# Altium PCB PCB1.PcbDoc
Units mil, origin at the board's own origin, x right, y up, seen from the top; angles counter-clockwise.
Board outline 2945 x 2892.01 mil, 2 copper layers (Top Layer, Bottom Layer); 40 components, 36 nets, 180 pads, 28 vias.
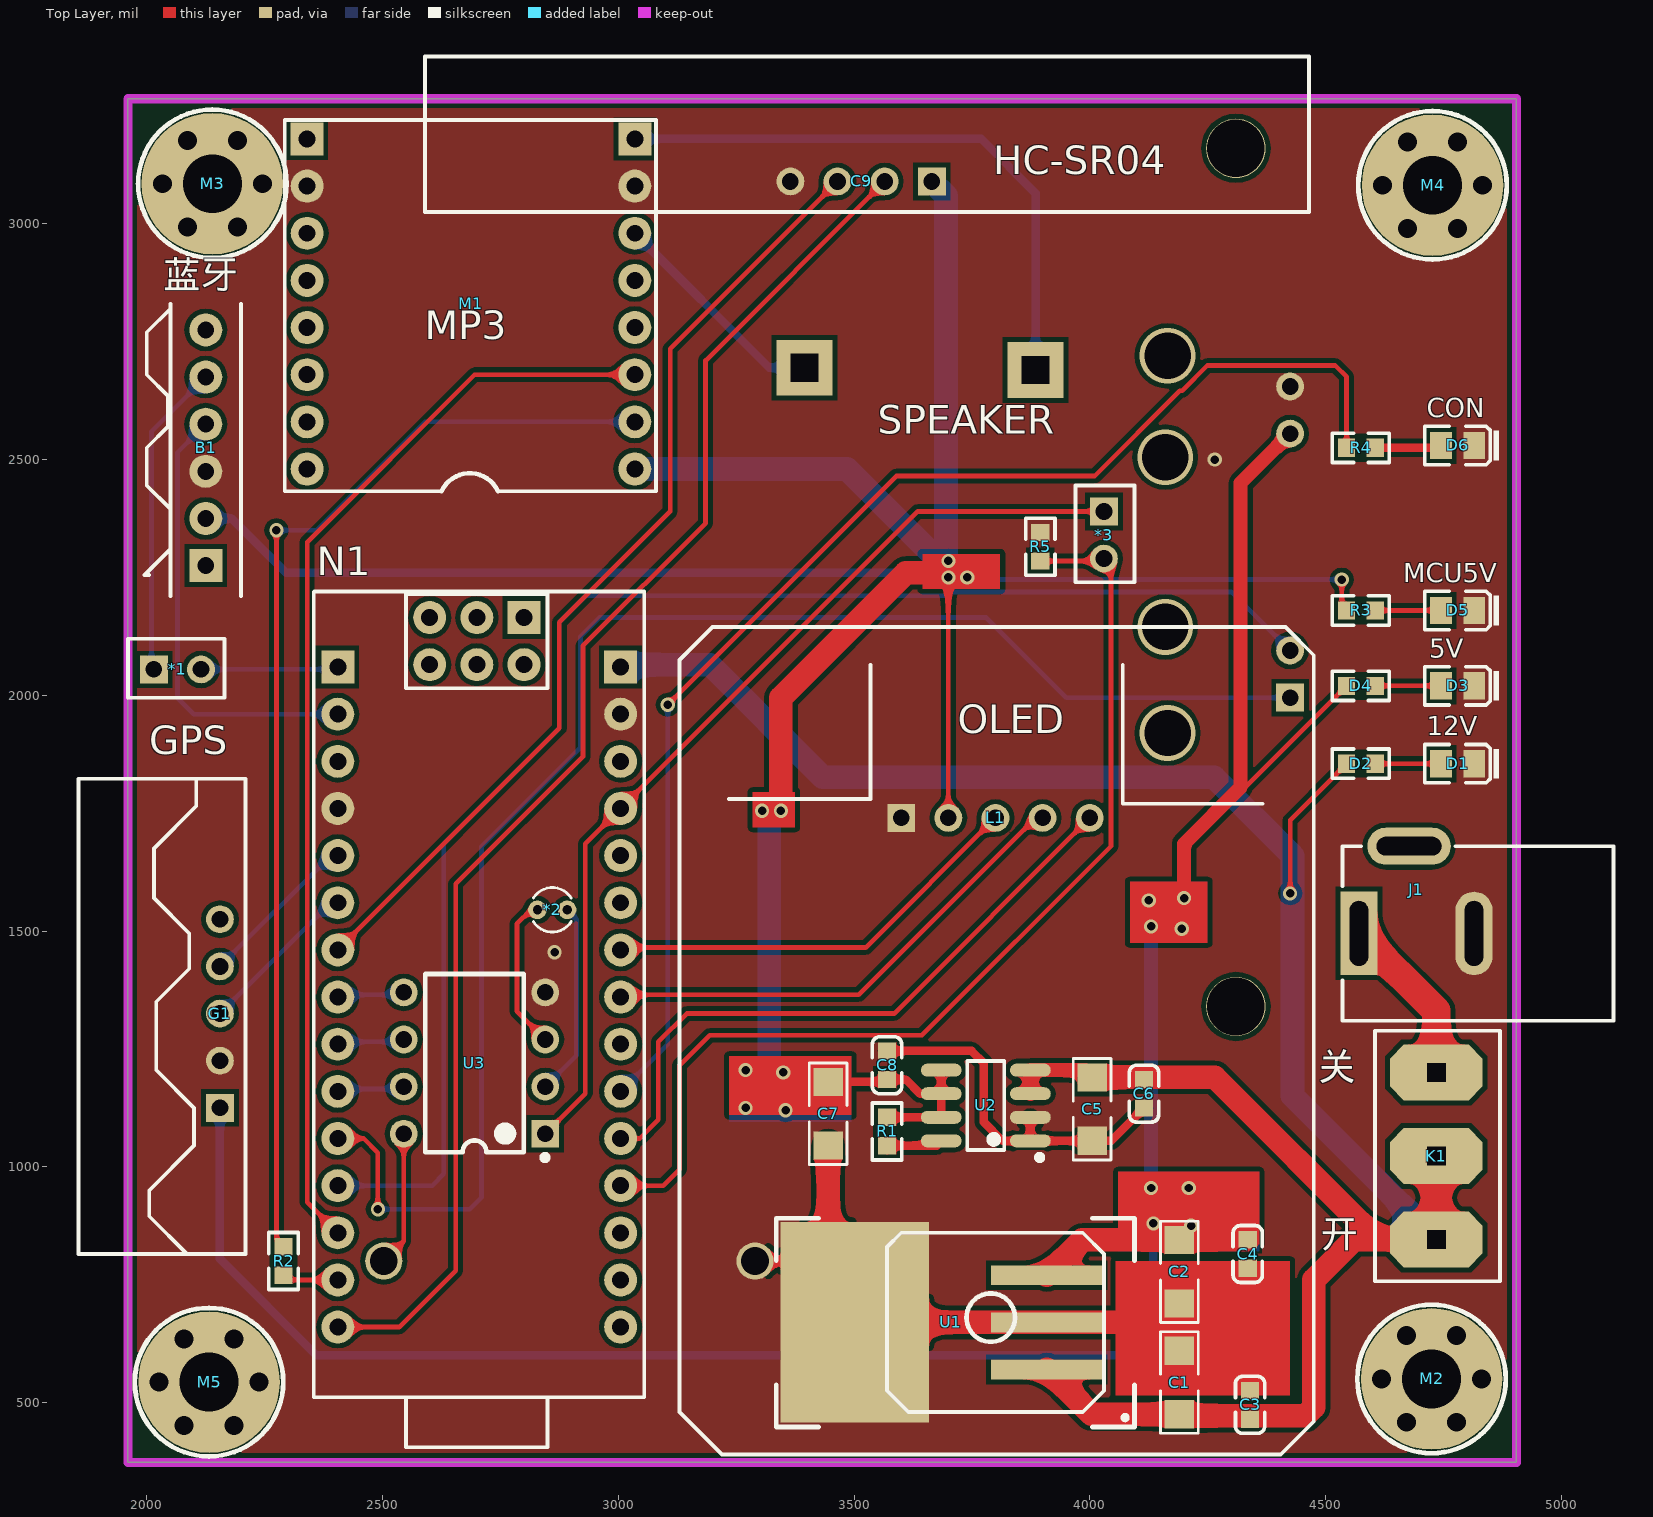
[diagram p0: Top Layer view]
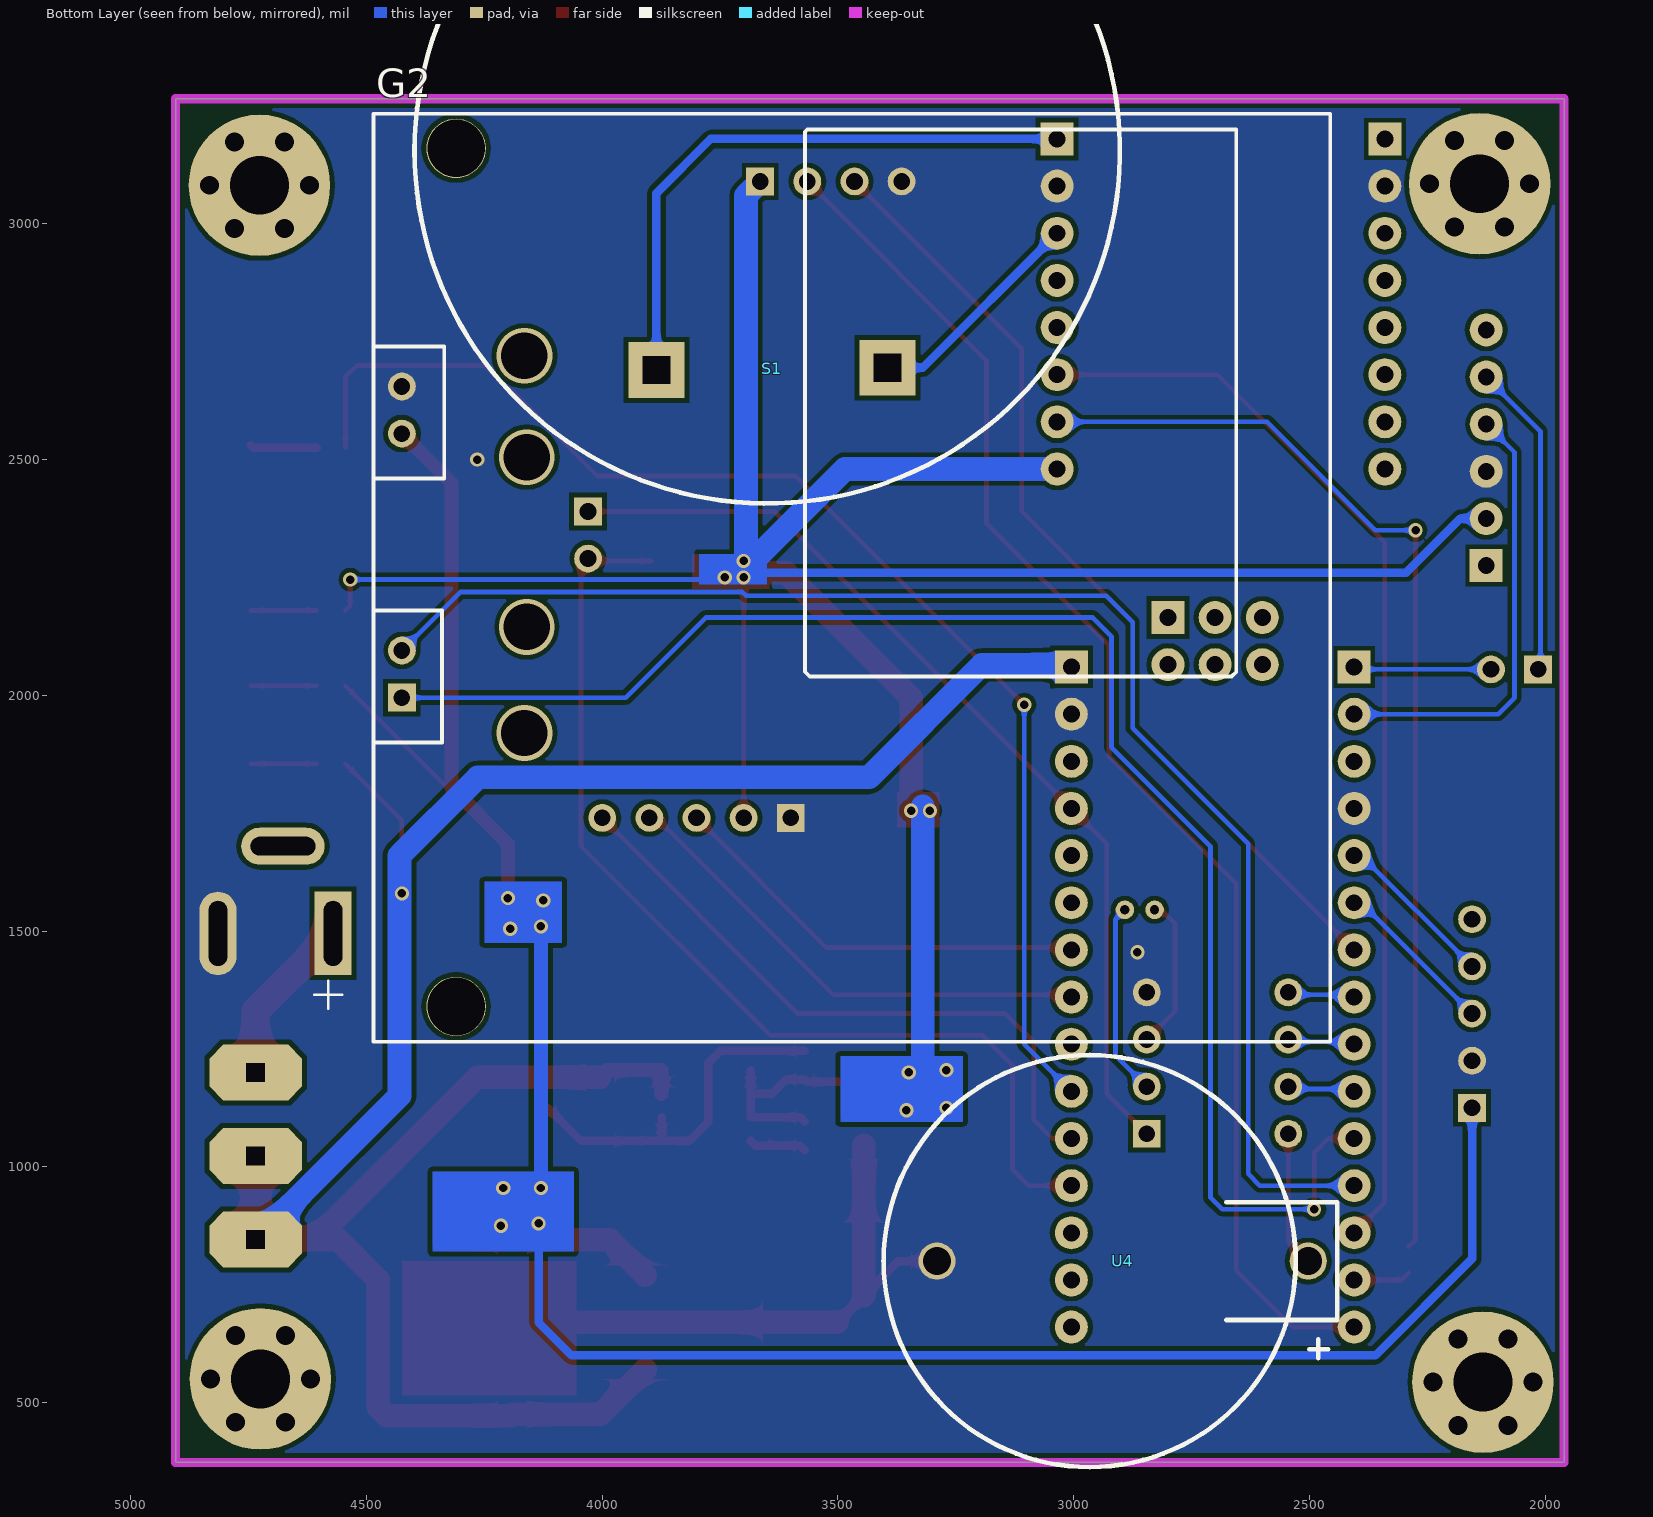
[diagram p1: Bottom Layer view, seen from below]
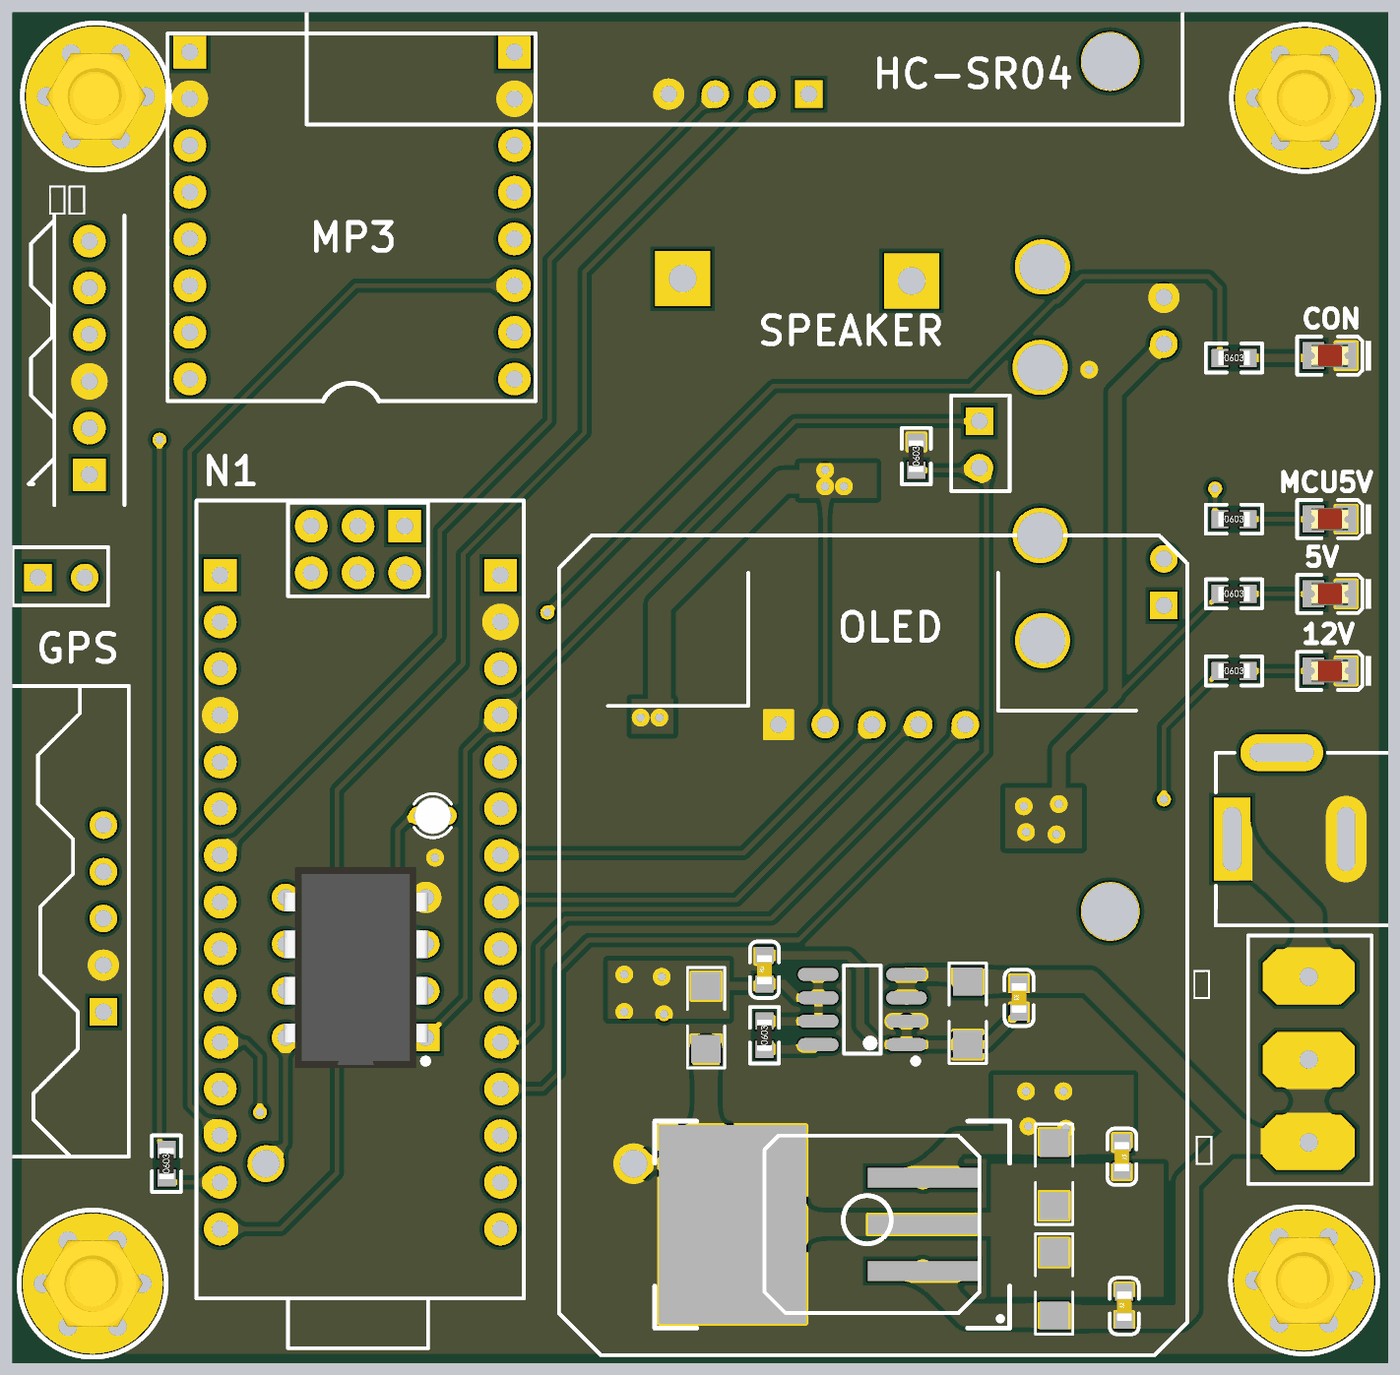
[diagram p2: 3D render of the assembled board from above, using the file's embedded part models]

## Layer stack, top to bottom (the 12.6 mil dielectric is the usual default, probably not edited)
Top Solder: solder mask 0.4, Solder Resist, Dk 3.5
Top Layer: signal copper 1.4
Dielectric 1: dielectric 12.6, FR-4, Dk 4.8
Bottom Layer: signal copper 1.4
Bottom Solder: solder mask 0.4, Solder Resist, Dk 3.5

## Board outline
1960,372.99 4905,372.99 4905,3265 1960,3265

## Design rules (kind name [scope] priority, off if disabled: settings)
Clearance [All] p1: gap=10
ComponentClearance [All] p1 off: gap=10 collisioncheckmode=3 verticalgap=10 showdistances=FALSE
PlaneConnect [All] p1: planeconnectstyle=Direct reliefexpansion=20 reliefentries=4 reliefconductorwidth=10 reliefairgap=10
PolygonConnect [All] p1: connectstyle=Direct reliefconductorwidth=10 reliefentries=4 polygonreliefangle="90 Angle" airgapwidth=10
RoutingVias [All] p1: holewidth=28 width=50 viastyle="Through Hole" minholewidth=28 minwidth=50 maxholewidth=28 maxwidth=50
SolderMaskExpansion [All] p1: expansion=4
Width [All] p1: maxlimit=99 minlimit=10 preferedwidth=18 minimp=50.000000 maximp=50.000000 favimp=50.000000
28 further rules are at their usual default settings.

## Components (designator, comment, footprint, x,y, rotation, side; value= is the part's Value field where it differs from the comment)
*1 "跳帽" 跳帽 1840,2120 r0 top
*2 "osc" OSC-2X6-LI 2860,1545 r0 top
*3 "光敏电阻" 跳帽 4095,2565 r270 top
B1 "BlueTOOLS" BLUETOOTH 2050,2455 r90 top
C1 "10uF" 1206 4190,475 r90 top
C2 "10uF" 1206 4190,844.65 r270 top
C3 "104" 0603_C 4340,495 r90 top
C4 "104" 0603_C 4335,815 r270 top
C5 "10uF" 1206 4005,1189.65 r270 top
C6 "104" 0603_C 4115,1155 r90 top
C7 "10uF" 1206 3445,1180 r270 top
C8 "103" 0603_C 3570,1215.31 r90 top
C9 "HC-SR04" HC-SR04 4415,3310 r180 top
D1 "蓝灯 0805" 0805_LED_S1 4780,1855 r180 top
D2 "Res2" 0603_R 4575,1855 r0 top
D3 "蓝灯 0805" 0805_LED_S1 4780,2020 r180 top
D4 "Res2" 0603_R 4575,2020 r0 top
D5 "蓝灯 0805" 0805_LED_S1 4780,2180 r180 top
D6 "白灯 0805" 0805_LED_S1 4780,2530 r180 top
G1 "GPS" GPS 1855,815 r90 top
G2 "GPRS" GPRS 4385,1265 r90 bottom
J1 "12DC插座" "DC插座 5.5mm*2.1mm" 4570.91,1495 r180 top
K1 "拨动开关" SW1 4600,755 r0 top
L1 "oled" OLED 3230,450 r0 top
M1 "MP3_MOD" MP3_MOD 3080,3220 r180 top
M2 "HDC3-3M5" M3X4固定孔 4725,550 r0 top
M3 "HDC3-3M5" M3X4固定孔 2139,3085 r0 top
M4 "HDC3-3M5" M3X4固定孔 4727,3081.8 r0 top
M5 "HDC3-3M5" M3X4固定孔 2132,543.2 r0 top
N1 "ArduinoNano" ArduinoNano 3055,510 r90 top
R1 "Res/250K" 0603_R 3570,1075 r90 top
R2 "1K" 0603_R 2290,800 r90 top
R3 "Res2" 0603_R 4575,2180 r0 top
R4 "1.5KΩ (1501) ±1%" 0603_R 4575,2525 r0 top
R5 "1KΩ" 0603_R 3895,2315 r90 top
S1 "SRKER" SPERKER 3650,3155 r180 bottom
U1 "LM2940" LM2940 3715,670 r180 top
U2 "TPS7350" SOIC8 3873.98,1055 r180 top
U3 "DS1302" DS1302 2695,1220 r180 top
U4 "CR2302" BATTERY-2032 2502.6,800 r0 bottom

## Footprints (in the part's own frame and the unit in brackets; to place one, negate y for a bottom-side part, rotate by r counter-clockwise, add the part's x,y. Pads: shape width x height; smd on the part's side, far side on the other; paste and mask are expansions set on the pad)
0603_C [mm]
  rect 0.93x0.98 smd: 1(-0.77,0) 2(0.77,0)
  silkscreen extent -1.54,-0.79 1.54,0.79, body extent -0.8,-0.4 0.8,0.4, height 0.3
0603_R [mm]
  rect 0.93x0.98 smd: 1(-0.77,0) 2(0.77,0)
  silkscreen extent -1.53,-0.79 1.54,0.79, body extent -0.85,-0.4 0.85,0.4, height 0.56
0805_LED_S1 [mm]
  rect 1.16x1.47 smd: A(0.89,0) K(-0.89,0)
  silkscreen extent -2.25,-1.04 1.77,1.03, body extent -1.01,-0.62 1.01,0.62, height 1.1
1206 [mm]
  rect 1.52x1.6 smd: 1(0,0) 2(3.42,0)
  silkscreen extent -1.02,-1.02 4.44,1.02
ArduinoNano [mil] "单片机插口"
  rect 70x70 hole 36: 1(1550,50) 30(1550,650) 36(1655,255)
  round 70 hole 36: 2(1450,50) 3(1350,50) 4(1250,50) 5(1150,50) 6(1050,50) 7(950,50) 8(850,50) 9(750,50) 10(650,50) 11(550,50) 12(450,50) 13(350,50) 14(250,50) 15(150,50) 16(150,650) 17(250,650) 18(350,650) 19(450,650) 20(550,650) 21(650,650) 22(750,650) 23(850,650) 24(950,650) 25(1050,650) 26(1150,650) 27(1250,650) 28(1350,650) 29(1450,650) 31(1555,455) 32(1655,455) 33(1555,355) 34(1655,355) 35(1555,255)
  silkscreen extent -105,0 1710,701
BATTERY-2032 [mm]
  round 2 hole 1.5: 1(0,0) 2(20,0)
  silkscreen extent -1.56,-11.1 22.88,11.1
BLUETOOTH [mil]
  rect 70x70 hole 36: 1(-180,-75)
  round 70 hole 36: 2(-80,-75) 3(20,-75) 4(120,-75) 5(220,-75) 6(320,-75)
  silkscreen extent -245,-150 375,0
"DC插座 5.5mm*2.1mm" [mm]
  rect 2x4.5 hole 1 slot 3.5 at 90 deg: 1(0,0)
  oval 2x4.5 hole 1 slot 3.5 at 90 deg: 2(-6.2,0)
  oval 4.5x2 hole 1 slot 3.5 at 0 deg: 3(-2.7,-4.7)
  silkscreen extent -13.72,-4.7 0.89,4.7
DS1302 [mm] "RTC实时时钟芯片"
  rect 1.5x1.5 hole 0.9: 1(-3.81,3.81)
  round 1.5 hole 0.9: 2(-3.81,1.27) 3(-3.81,-1.27) 4(-3.81,-3.81) 5(3.81,-3.81) 6(3.81,-1.27) 7(3.81,1.27) 8(3.81,3.81)
  silkscreen extent -3.95,-4.8 2.65,5.24, body extent -3.93,-5.46 3.94,5.46, height 5.08
GPRS [mm]
  round 1.5 hole 0.9: 1(32.766,1.016) 2(21.082,1.016) 4(35.306,1.016)
  rect 1.5x1.5 hole 0.9: 3(18.542,1.016)
  round 3.2 hole 3.1: ""(1.905,-1.905) ""(48.133,-1.905)
  silkscreen extent 0,-49 50,2.54
GPS [mm]
  rect 1.5x1.5 hole 0.9: 1(7.874,-7.62)
  round 1.5 hole 0.9: 2(10.414,-7.62) 3(12.954,-7.62) 4(15.494,-7.62) 5(18.034,-7.62)
  silkscreen extent 0,-9 25.6,0
HC-SR04 [mm] "超声波模块"
  rect 1.5x1.5 hole 0.9: 1(19.05,5.588)
  round 1.5 hole 0.9: 2(21.59,5.588) 3(24.13,5.588) 4(26.67,5.588)
  silkscreen extent -1.27,-1.14 46.35,7.24
LM2940 [mm] "LM2940"
  rect 6x1.07 smd: 1(-4.925,2.54) 2(-4.925,0) 3(-4.925,-2.54)
  rect 8x10.8 smd: 2(5.41,0)
  silkscreen extent -9.65,-5.61 9.65,5.64, body extent -4.45,-5.21 4.45,5.21, height 4.65
M3X4固定孔 [mil] "M3铜柱，长：4mm，螺纹长：6mm"
  round 40 hole 40: 1(-106,0) 1(-53,-91.8) 1(-53,91.8) 1(53,-91.8) 1(53,91.8) 1(106,0)
  round 300 hole 125: 1(0,0)
  silkscreen extent -157,-157 157,157, body extent -106,-93 106,93, height 159
MP3_MOD [mil]
  round 70 hole 36: 1(45,740) 2(45,640) 3(45,540) 4(45,440) 5(45,340) 6(45,240) 7(45,140) 10(740,140) 11(740,240) 12(740,340) 13(740,440) 14(740,540) 15(740,640) 16(740,740)
  rect 70x70 hole 36: 8(45,40) 9(740,40)
  silkscreen extent 0,0 787,787
OLED [mm] "0.96寸带五轴按键"
  rect 1.5x1.5 hole 0.9: 1(9.398,32.766)
  round 1.5 hole 0.9: 2(11.938,32.766) 3(14.478,32.766) 4(17.018,32.766) 5(19.558,32.766)
  silkscreen extent -2.54,-1.52 31.62,43.05
OSC-2X6-LI [mm] "脚距：1.6mm"
  round 1 hole 0.5: 1(0.8,0) 2(-0.8,0)
  silkscreen extent -1.02,-1.2 1.02,1.2, body extent -1,-1 1,1, height 7.1
SOIC8 [mm]
  oval 2.2x0.7 smd: 1(0,0) 2(0,-1.27) 3(0,-2.54) 4(0,-3.81) 5(4.8,-3.81) 6(4.8,-2.54) 7(4.8,-1.27) 8(4.8,0)
  silkscreen extent -0.65,-4.31 3.4,1.04
SPERKER [mm]
  rect 3x3 hole 1.5 square: 1(-5.969,-11.811) 2(6.477,-11.684)
  silkscreen extent -19,-19 19,19
SW1 [mm]
  oct 5x3 hole 1 square: 1(3.429,11.303) 2(3.429,6.803) 3(3.429,2.303)
  silkscreen extent 0.13,0.05 6.86,13.55
跳帽 [mm]
  rect 1.5x1.5 hole 0.9: 1(4.445,-1.651)
  round 1.5 hole 0.9: 2(6.985,-1.651)
  silkscreen extent 3.05,-3.17 8.25,0

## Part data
*3: library part 跳帽
C1 C2 C5 C7: library part 电解电容, "Capacitor"
C3 C4 C6 C8: library part 普通电容, "Capacitor"
D1 D3 D5: library part "0805 蓝灯", "发光二极管"
D2 D4 R3: "Resistor"
D6: library part "0805 白灯", "发光二极管"
J1: library part DC插座
R1: library part Res2, "Resistor"
R2: library part "0603 1.1KΩ (1101) 1%", "贴片电阻"
R4 R5: library part "0603 1.5KΩ (1501) 1%", "贴片电阻"
U1: library part 78L05, "CI-78L05"

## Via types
v1: diameter 30, hole 18, Top Layer to Bottom Layer, 24 vias
v2: diameter 118.11, hole 98.43, Top Layer to Bottom Layer, 4 vias

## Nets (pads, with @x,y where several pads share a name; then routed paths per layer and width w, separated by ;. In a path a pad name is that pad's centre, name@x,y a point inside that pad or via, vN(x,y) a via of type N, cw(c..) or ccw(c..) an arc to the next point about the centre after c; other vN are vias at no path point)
5V: *3.1 N1.4 U3.1 | length 2042.2
  Top Layer w10: U3.1 2930,1155 2930,1685 N1.4 3635,2390 *3.1
12V: C1.1 C3.1 C5.1 C6.2 D2.1 K1.2 K1.3 N1.1 U1.1 U2.3 U2.4 | length 5139.3
  Top Layer w10: v1(4425,1580) 4425,1735.31 D2.1
  Top Layer w30: U2.3 U2.4 3989.65,1205 C5.1
  Top Layer w50: U1.1 4003.9,475 C1.1 4192.99,472.01 4457.01,472.01 4475,490 4475,760 4560.67,845.67 4609.33,845.67 ; C5.1 4005.35,1190 4265,1190 4609.33,845.67 ; K1.3 4609.33,845.67
  Top Layer w60: K1.3 K1.2
  Bottom Layer w50: N1.1@3015,2065 3195,2065 3434.06,1825.94 4264.06,1825.94 4430,1660 4430,1150.67 K1.3
B_RX: B1.4 N1.29 | length 959.4
  Bottom Layer w10: B1.4 2065,2515 2065,1995 2100,1960 N1.29
B_TX: *1.2 N1.30 | length 292.1
  Bottom Layer w10: *1.2 2400,2055 N1.30
CONTROL_LED: N1.10 R4.1 | length 2759.5
  Top Layer w10: v1(3105,1980) 3590,2465 4010,2465 4190.94,2645.94 4195.67,2645.94 4249.26,2699.53 4520.47,2699.53 4544.69,2675.31 R4.1
  Bottom Layer w10: N1.10 3105,1260 v1(3105,1980)
DS3V3: U3.8 U4.1 | length 287.6
  Top Layer w10: U4.1 2545,842.4 U3.8
ECHO: C9.3 N1.24 | length 2069.1
  Top Layer w10: N1.24 2875,1930 2875,2155 3110,2390 3110,2735 C9.3
GND: B1.3 C1.2 C2.2 C3.2 C4.2 C5.2 C6.1 C7.2 C8.2 C9.4 D1.K D3.K D5.K D6.K G1.2 G2.4 J1.2 L1.1 M1.7 M1.10 N1.2 N1.27 R5.2 U1.2 U2.1 U2.2 U3.4 U4.2 | length 2446
  Top Layer w18: U4.2 3372,800 3445,727 U1.2@3502,670 ; C8.2 3749.37,1245.63 3775,1220 3775,1095 3815,1055 U2.1 ; U2.2 U2.1 ; C6.1 4045.31,1055 C5.2 U2.1 ; C1.2 4255.67,609.65 C3.2 ; C2.2 4264.69,784.69 C4.2
  Top Layer w50: U1.2@3445,727 C7.2 ; U1.2@3502,670 3908.9,670 4150,670 4150,649.65 C1.2
  other v1: 2865,1455 4265,2500
GPRS_RX: G2.3 N1.20 | length 3316.8
  Top Layer w10: N1.20 2460,1060 2490,1030 v1(2490,910)
  Bottom Layer w10: v1(2490,910) 2685,910 2710,935 2710,1680 2920,1890 2920,2125 2960,2165 3780,2165 3950,1995 G2.3
GPRS_TX: G2.2 N1.19 | length 3134.8
  Bottom Layer w10: N1.19 2605,960 2630,985 2630,1685 2875,1930 2875,2155 2931,2211 3694.94,2211 3703,2219.06 4300.95,2219.06 G2.2
GPS_RX: G1.4 N1.26 | length 347.3
  Bottom Layer w10: G1.4 2390,1660 N1.26
GPS_TX: G1.3 N1.25 | length 347.3
  Bottom Layer w10: G1.3 2390,1560 N1.25
MP3_RX: M1.3 N1.18 | length 2334
  Top Layer w10: N1.18 2340,925 2340,2325 2695,2680 M1.3
MP3_TX: N1.17 R2.1 | length 121.1
  Top Layer w10: R2.1@2290,774.69 2304.68,760 N1.17
Net*1_1: *1.1 B1.5 | length 662.6
  Bottom Layer w10: *1.1@2010,2060 2010,2560 B1.5
Net*2_1: *2.1 U3.2 | length 410.8
  Bottom Layer w10: U3.2 2911.5,1236.5 2911.5,1525 *2.1
Net*2_2: *2.2 U3.3 | length 325.8
  Top Layer w10: *2.2 2815,1545 2785,1515 2785,1330 U3.3
NetD1_A: D1.A D2.2 | length 139.6
  Top Layer w10: D2.2 D1.A
NetD3_A: D3.A D4.2 | length 139.6
  Top Layer w10: D4.2 D3.A
NetD5_A: D5.A R3.2 | length 139.6
  Top Layer w10: R3.2 D5.A
NetD6_A: D6.A R4.2 | length 141.7
  Top Layer w18: R4.2 4739.96,2525 D6.A
NetJ1_1: J1.1 K1.1 | length 363
  Top Layer w60: J1.1 4735,1330.91 K1.1
NetM1_2: M1.2 R2.2 | length 2381.2
  Top Layer w10: v1(2275,2350) 2275,845.32 R2.2
  Bottom Layer w10: v1(2275,2350) 2360,2350 2590,2580 M1.2
NetM1_6: M1.6 S1.2 | length 478.1
  Bottom Layer w18: M1.6 3320,2695 S1.2
NetM1_8: M1.8 S1.1 | length 1272.6
  Bottom Layer w18: M1.8 3770,3180 3885,3065 S1.1
NetR1_1: R1.1 U2.8 | length 123.4
  Top Layer w18: R1.1@3570,1034.69 3580.31,1045 3675,1045 U2.8
PIN_CLK: N1.21 U3.7 | length 132.1
  Bottom Layer w10: N1.21@2415,1165 2540,1165 U3.7
PIN_DAT: N1.22 U3.6 | length 132.1
  Bottom Layer w10: N1.22@2415,1265 2540,1265 U3.6
PIN_RET: N1.23 U3.5 | length 132.1
  Bottom Layer w10: N1.23@2415,1365 2540,1365 U3.5
S1: L1.5 N1.11 | length 1394.5
  Top Layer w10: N1.11 3045,1060 3085,1100 3085,1265 3145,1325 3585,1325 L1.5
  Bottom Layer w10: N1.11@3015,1065 N1.11@3030,1050
S2: *3.2 N1.12 R5.1 | length 2220.5
  Top Layer w10: N1.12 3095,960 3130,995 3130,1215 3193.94,1278.94 3643.94,1278.94 4045,1680 4045,2275 *3.2 4024.69,2284.69 R5.1
SCL: L1.3 N1.7 | length 898.9
  Top Layer w10: N1.7@3015,1465 3525,1465 L1.3
SDA: L1.4 N1.8 | length 1040.3
  Top Layer w10: N1.8@3015,1365 3510,1365 3885,1740 L1.4
TRG: C9.2 N1.16 | length 2986.6
  Top Layer w10: N1.16 2535,660 2655,780 2655,1600 2925,1870 2925,2105 3185,2365 3185,2710 C9.2
VCC_5V: C2.1 C4.1 D4.1 G1.1 G2.1 U1.3 | length 5216.9
  Top Layer w10: 4200,1675.31 D4.1
  Top Layer w30: v1(4200,1570) 4200,1675.31 4200,1685 4320,1805 4320,2450 G2.1
  Top Layer w50: U1.3 3984.21,845.31 C4.1
  Bottom Layer w18: G1.1 2155,805 2360,600 4065,600 4135,670 v1(4135,880)
  Bottom Layer w30: v1(4130,955) 4130,1525
  other v1: 4215,875 4210,955 4195,1505 4130,1510 4125,1565
VCC_MCU5V: B1.2 C7.1 C8.1 C9.1 L1.2 M1.1 R1.2 R3.1 U2.5 U2.6 U2.7 | length 6409.7
  Top Layer w10: L1.2 v1(3700,2250) ; v1(4534.53,2245.47) 4534.53,2190.16 R3.1
  Top Layer w18: C7.1 3565,1180 C8.1 3610,1185 3640,1155 U2.6 ; R1.2@3570,1095.32 3579.68,1105 U2.7 U2.6 ; U2.5 U2.6
  Top Layer w50: v1(3345,1755) 3345,1995 3610,2260 3690,2260 v1(3700,2250)
  Bottom Layer w10: v1(3700,2250) 3704.53,2245.47 v1(4534.53,2245.47)
  Bottom Layer w18: B1.2 2180,2375 2295,2260 3690,2260 v1(3700,2250)
  Bottom Layer w50: M1.1 3485,2480 3695,2270 3695,3060 C9.1 ; 3320,1160 3320,1765
  other v1: 3355,1120 3270,1125 3350,1200 3270,1205 3305,1755 3740,2250 3700,2285
pads on no net: B1.1 B1.6 G1.5 G2. J1.3 M1.4 M1.5 M1.9 M1.11 M1.12 M1.13 M1.14 M1.15 M1.16 M2.1 M3.1 M4.1 M5.1 N1.3 N1.5 N1.6 N1.9 N1.13 N1.14 N1.15 N1.28 N1.31 N1.32 N1.33 N1.34 N1.35 N1.36
copper on no net:
  other v2: 4165,1920 4160,2145 4160,2505 4165,2720

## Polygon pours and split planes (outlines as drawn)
GND on Bottom Layer "Bottom Layer-No Net" (solid, remove dead copper, pour order 0): 1695,3455 1485,3245 1485,-15 5485,-15 5615,115 5970,470 5970,3710
GND on Top Layer "Bottom Layer-No Net" (solid, remove dead copper, pour order 2): 1715,3805 1715,-165 1840,-290 2010,-120 6205,-120 6205,3620 5995,3830

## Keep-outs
Keep-Out Layer:
  the board outline again, w19.68

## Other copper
Top Layer:
  rectangle net VCC_5V: 4085,1475 4250,1605
  rectangle net VCC_MCU5V: 3645,2225 3810,2300
  rectangle net VCC_MCU5V: 3285,1720 3375,1795
  rectangle net VCC_MCU5V: 3235,1110 3495,1235
  rectangle net GND: 4055,515 4425,800
  rectangle net VCC_5V: 4060,835 4360,990
Bottom Layer:
  rectangle net VCC_5V: 4060,820 4360,990
  rectangle net VCC_MCU5V: 3650,2235 3795,2300
  rectangle net VCC_MCU5V: 3235,1095 3495,1235
  rectangle net VCC_5V: 4085,1475 4250,1605

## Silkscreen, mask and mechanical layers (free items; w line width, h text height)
Top Overlay:
  lines w8: 2005,2255 1995,2255 2050,2310 2050,2395 2000,2445 2000,2525 2045,2570 2045,2635 2000,2680 2000,2770 2050,2820 2050,2830 ; 2085,815 2005,895 2005,950 2100,1045 2100,1125 2020,1205 2020,1350 2090,1420 2090,1495 2015,1570 2015,1675 2105,1765 2105,1822.87
  text "HC-SR04" at 3795,3105 h60
  text "蓝牙" at 2035,2845 h100
  text "MP3" at 2590,2755 h60
  text "CON" at 4715,2590 h40
  text "SPEAKER" at 3550,2555 h60
  text "MCU5V" at 4665,2240 h40
  text "5V" at 4720,2080 h40
  text "OLED" at 3720,1920 h60
  text "12V" at 4715,1915 h40
  text "GPS" at 2005,1875 h60
  text "关" at 4485,1165 h100
  text "开" at 4490,810 h100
